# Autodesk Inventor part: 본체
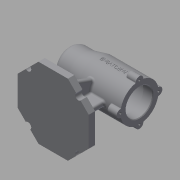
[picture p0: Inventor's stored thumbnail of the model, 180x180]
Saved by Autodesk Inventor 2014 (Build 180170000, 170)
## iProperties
Created: 2019-12
Part Number: 본체
Material: Generic
Document SubType Name: Modeling
Designer: kh
Density: 1 g/cm^3
Appearance: Default
Author: kh
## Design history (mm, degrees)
sketch "Sketch1"
  geometry: L1 (-56, 23.196)-(-23.196, 56); L2 (-23.196, 56)-(23.196, 56); L3 (23.196, 56)-(56, 23.196); L4 (56, 23.196)-(56, -23.196); L5 (56, -23.196)-(23.196, -56); L6 (23.196, -56)-(-23.196, -56); L7 (-23.196, -56)-(-56, -23.196); L8 (-56, -23.196)-(-56, 23.196); 3 further points
  constraints: 16 end point, 1 coincident, 1 horizontal alignment, 1 midpoint, 17 other
  dimensions: "d0" = 56 distance from line of L4 point (0, 0)
extrude "Extrusion1" new body sketch "Sketch1" distance "d1" = 10; taper "d2" = 0 deg
sketch "Sketch2"
  geometry: L1 (-23.196, 56)-(-56, 23.196) reference; C1 r 5 at (-39.598, 39.598); 1 further point
  constraints: 1 centre point, 1 midpoint
  dimensions: "d84" = 10 diameter of C1
extrude "Extrusion2" cut sketch "Sketch2" stored distance "d4" = 10; taper "d5" = 0 deg
pattern_circular "Circular Pattern1" dims angle "d7" = 360 deg
sketch "Sketch4"
  geometry: L1 (-72.491, 80)-(124.7, 80); L2 (43.134, 0)-(34.598, 0) reference; L3 (-56, 80)-(-56, 105); L4 (-56, 105)-(-31, 105); L5 (-31, 105)-(-11, 110); L6 (-11, 110)-(56, 110); L7 (56, 110)-(56, 101); L8 (56, 101)-(41, 101); L9 (41, 101)-(41, 104); L10 (41, 104)-(-13, 104); L11 (-13, 104)-(-13, 101); L12 (-13, 101)-(-25, 101); L13 (-25, 101)-(-25, 97.5); L14 (-25, 97.5)-(-43, 97.5); L15 (-43, 97.5)-(-43, 96); L16 (-43, 96)-(-47, 96); L17 (-47, 96)-(-47, 90.5); L18 (-47, 90.5)-(-50, 90.5); L19 (-50, 90.5)-(-50, 80); L20 (-56, 80)-(-50, 80); 3 further points
  constraints: 38 end point, 9 perpendicular, 7 parallel, 2 point on line, 1 collinear, 1 horizontal, 1 vertical alignment
  dimensions: "d9" = 80 distance between parallel lines of L2 L1; "d10" = 60 diameter of L6 L1; "d11" = 50 diameter of L4 L1; "d13" = 21 diameter of L18 L1; "d16" = 42 diameter of L12 L1; "d18" = 35 diameter of L14 L1; "d19" = 32 diameter of L16 L1; "d20" = 48 diameter of L10 L1; "d21" = 42 diameter of L8 L1; "d22" = 25 distance of L3.end L4.end; "d23" = 45 horizontal distance of L3.end L5.end; "d25" = 3 distance of L17.end L18.end; "d26" = 4 distance of L15.end L16.end; "d27" = 18 distance of L13.end L14.end; "d28" = 12 distance of L11.end L12.end; "d29" = 54 distance of L9.end L10.end; "d30" = 15 distance of L7.end L8.end; "d31" = 112 distance between parallel lines of L3 L7
revolve "Revolution1" sketch "Sketch4" stored, may be unused: angle "d32" = 90 deg
fillet "Fillet1" dims "d33" = 3
sketch "Sketch5"
  geometry: A1 r 30 centre (0, 0) between (0, 30) and (5.97, 29.4) reference; A2 r 6 centre (0, 30) between (5.97, 29.4) and (-5.97, 29.4); 1 further point
  constraints: 5 point on circle, 1 centre point, 1 vertical alignment
  dimensions: "d34" = 6 radius of A2
extrude "Extrusion3" join sketch "Sketch5" distance "d35" = 16; taper "d36" = 0 deg
sketch "Sketch7"
  geometry: L1 (23.196, 10)-(-23.196, 10) reference; L2 (31, 10)-(31, 56); L3 (41, 56)-(-13, 56) reference; L4 (56, 0)-(56, 10) reference; L5 (-56, 0)-(-56, 10) reference; L6 (-38, 10)-(-16.55, 56); L7 (-43.134, 10)-(-56, 10) reference; L8 (31, 56)-(-16.55, 56); L9 (-38, 10)-(31, 10); 1 further point
  constraints: 8 end point, 3 perpendicular, 2 point on line, 1 parallel
  dimensions: "d37" = 25 distance between parallel lines of L4 L2; "d38" = 18 distance from line of L5 L6.start; "d39" = 115 deg angle of L7 L6
extrude "Extrusion4" join sketch "Sketch7" stored distance "d40" = 8; taper "d41" = 0 deg
sketch "Sketch8"
  geometry: L1 (10, -23.196)-(10, 23.196) reference; L2 (10, 23.196)-(10, 36.062) reference; L3 (10, -56)-(10, -43.134) reference; L4 (0, -56)-(10, -56) reference; L5 (10, -36)-(56.766, -18.979); L6 (10, -36)-(10, 36); L7 (0, 56)-(10, 56) reference; L8 (10, 43.134)-(10, 56) reference; L9 (10, 36)-(56.766, 18.979); L10 (56.766, 18.979)-(56.766, -18.979); A1 r 30 centre (80, 0) between (50.268, -4) and (50.268, 4) reference; A2 r 30 centre (80, 0) between (56.766, 18.979) and (56.766, -18.979); 1 further point
  constraints: 8 end point, 5 point on circle, 1 centre point, 1 coincident, 1 collinear, 1 vertical alignment
  dimensions: "d44" = 20 distance from line of L4 L5.start; "d45" = 20 distance from line of L7 L6.end; "d48" = 110 deg angle of L3 L5; "d49" = 110 deg angle of L8 L9
fillet "Fillet4" dims "d54" = 3
fillet "Fillet5" dims "d55" = 1
hole "Hole1" diameter "d58" = 3.242; stored, may be unused: countersink angle "d62" = 90 deg, drill point angle "d64" = 118 deg; dims "d56" = 10, "d57" = 10, "d59" = 8, "d60" = 4, "d61" = 2, "d63" = 11
pattern_circular "Circular Pattern2" dims "d66" = 360 deg
fillet "Fillet6" dims "d68" = 10
extrude "Extrusion6" join sketch "Sketch8" distance "d69" = 8; taper "d70" = 0 deg
fillet "Fillet7" dims "d71" = 3
fillet "Fillet8" dims "d72" = 3
fillet "Fillet9" dims "d73" = 0.3
fillet "Fillet10" dims "d74" = 3
sketch "Sketch10"
  geometry: L1 (79.196, 74.002)-(79.196, 85.998) reference; 3 further points
  constraints: 1 horizontal alignment, 1 midpoint, 1 other
  dimensions: "d75" = 41 distance of point (79.196, 80) point (38.196, 80)
emboss "Emboss1" sketch "Sketch10" dims "d76" = 0.5, "d77" = 0
fillet "Fillet11" dims "d80" = 3
chamfer "Chamfer1" distance "d81" = 1; stored, may be unused: second distance "d82" = 2, angle "d83" = 45 deg
body "Solid1"
other parameters: "d46" = 110 deg
